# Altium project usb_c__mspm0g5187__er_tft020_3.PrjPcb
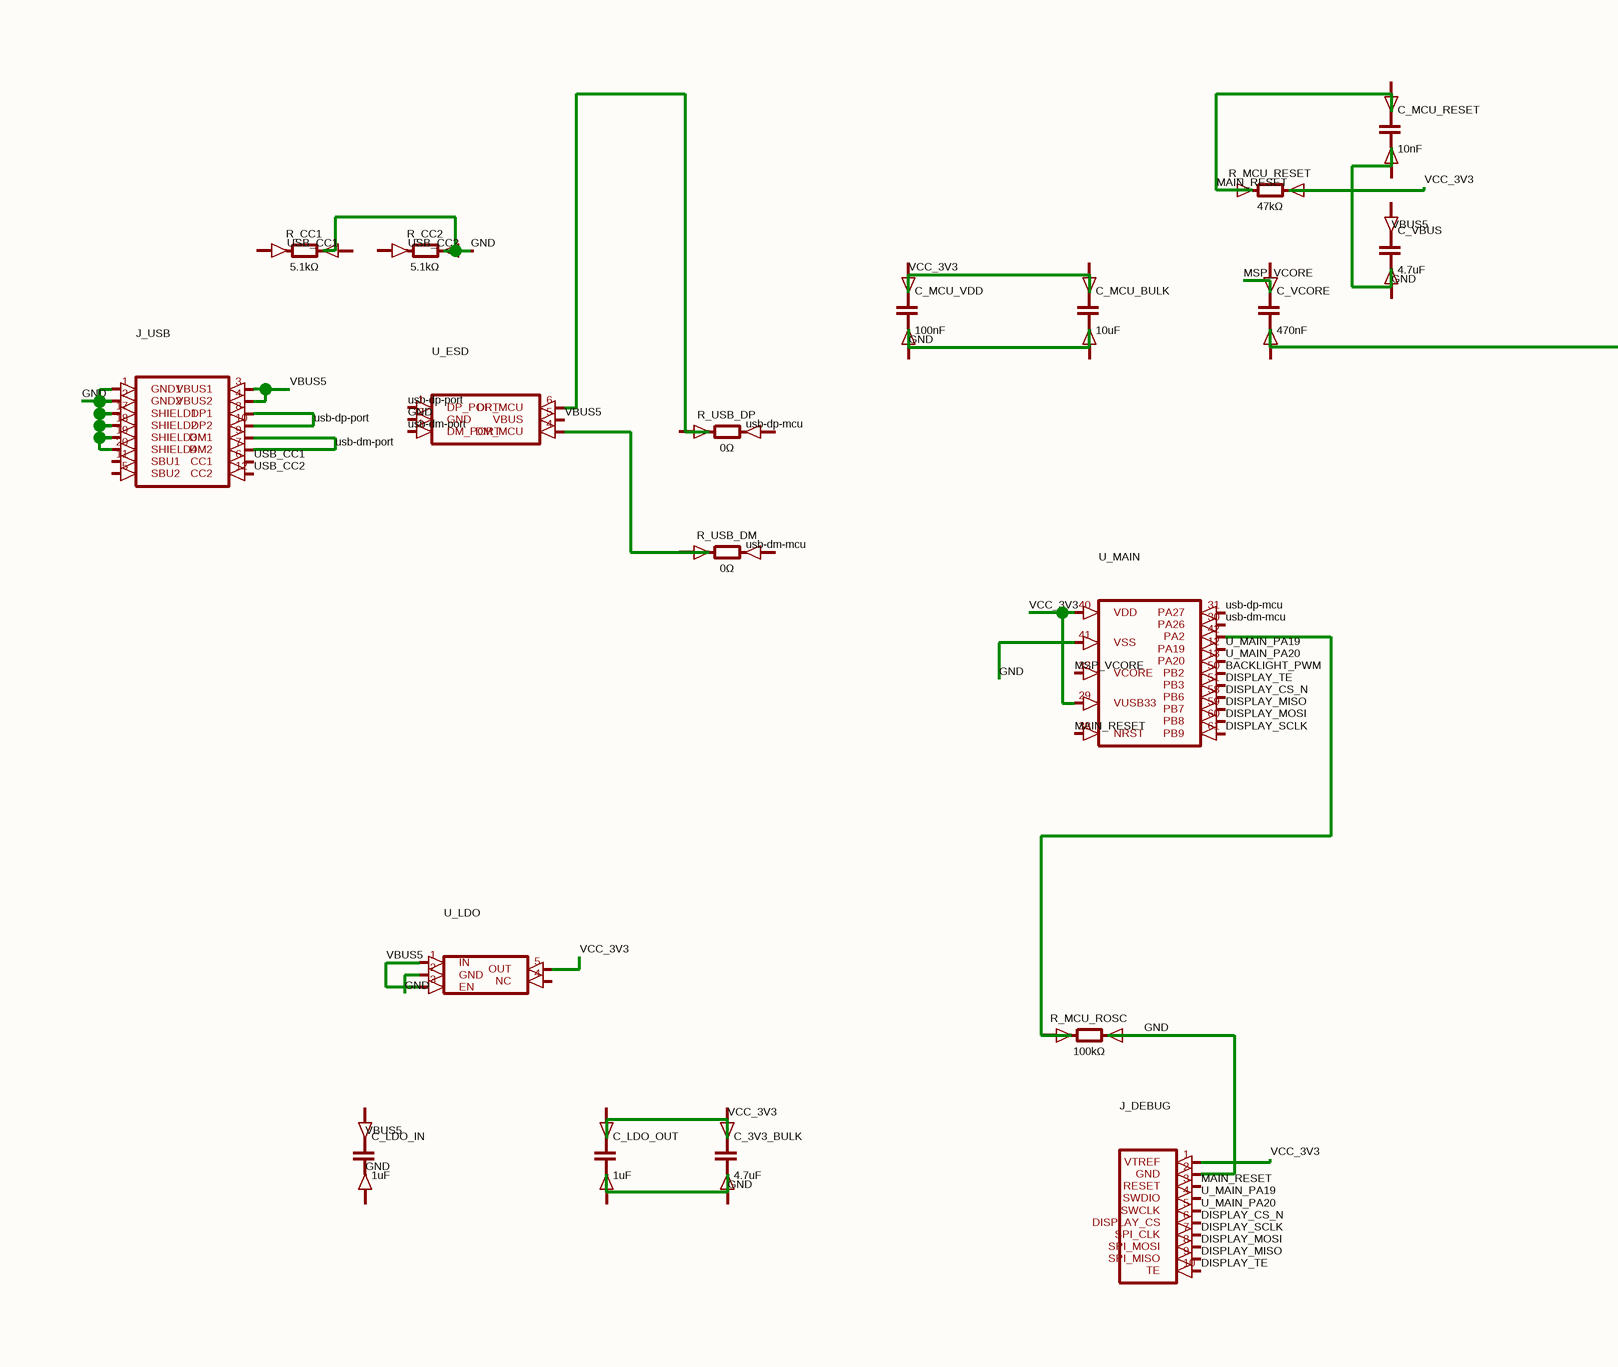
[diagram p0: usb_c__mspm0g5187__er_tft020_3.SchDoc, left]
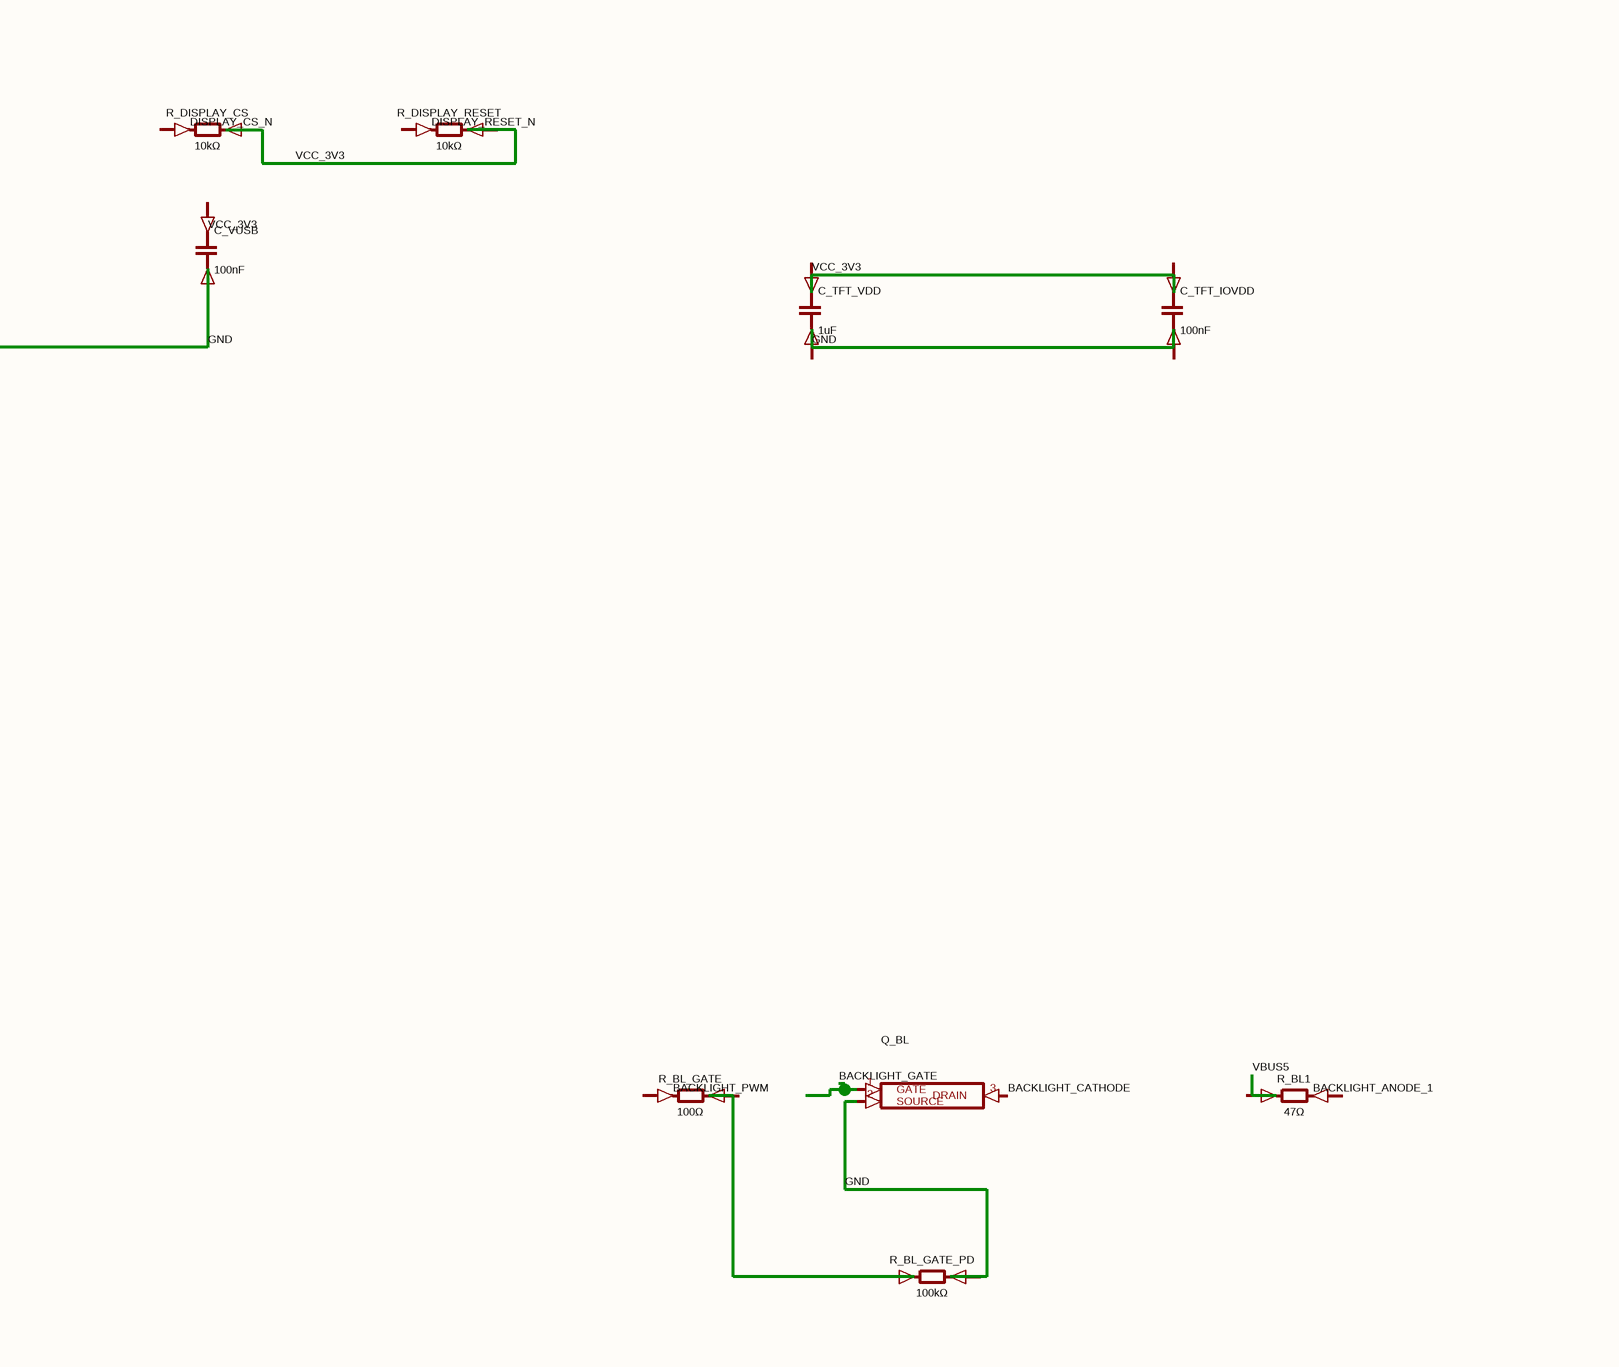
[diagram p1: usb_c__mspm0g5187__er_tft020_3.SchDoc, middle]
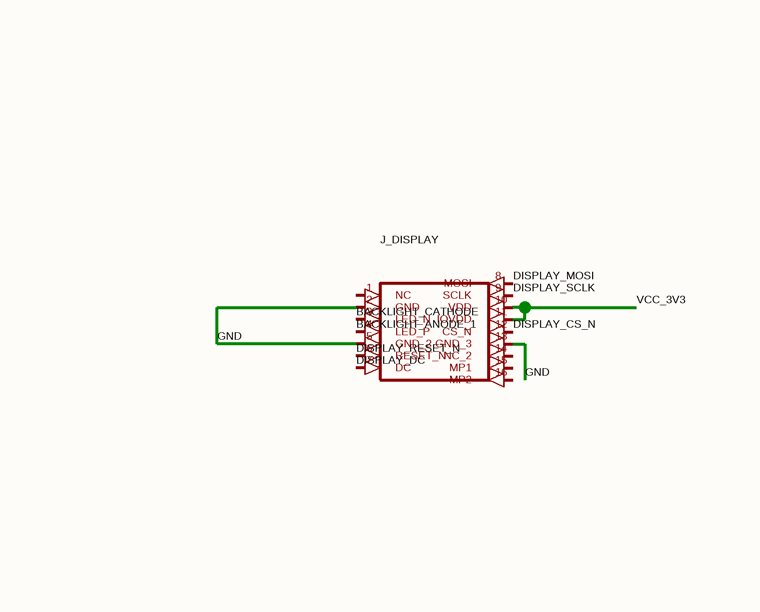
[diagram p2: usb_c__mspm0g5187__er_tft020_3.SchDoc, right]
1 sheet, 29 parts. Net scope: global (net labels, ports and power ports of the same name join across sheets).
Board file: usb_c__mspm0g5187__er_tft020_3.PcbDoc

## Sheet usb_c__mspm0g5187__er_tft020_3.SchDoc
size 386 x 150 mm

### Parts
C_3V3_BULK  4.7uF
C_LDO_IN  1uF
C_LDO_OUT  1uF
C_MCU_BULK  10uF
C_MCU_RESET  10nF
C_MCU_VDD  100nF
C_TFT_IOVDD  100nF
C_TFT_VDD  1uF
C_VBUS  4.7uF
C_VCORE  470nF
C_VUSB  100nF
J_DEBUG  (no value)
J_DISPLAY  (no value)
J_USB  (no value)
Q_BL  (no value)
R_BL1  47Ω
R_BL_GATE  100Ω
R_BL_GATE_PD  100kΩ
R_CC1  5.1kΩ
R_CC2  5.1kΩ
R_DISPLAY_CS  10kΩ
R_DISPLAY_RESET  10kΩ
R_MCU_RESET  47kΩ
R_MCU_ROSC  100kΩ
R_USB_DM  0Ω
R_USB_DP  0Ω
U_ESD  (no value)
U_LDO  (no value)
U_MAIN  (no value)

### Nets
BACKLIGHT_ANODE_1: J_DISPLAY.4(LED_P)
BACKLIGHT_CATHODE: J_DISPLAY.3(LED_N) Q_BL.3(DRAIN)
BACKLIGHT_GATE: Q_BL.1(GATE)
BACKLIGHT_PWM: U_MAIN.50(PB2)
DISPLAY_CS_N: J_DEBUG.6(DISPLAY_CS) J_DISPLAY.12(CS_N) U_MAIN.58(PB6)
DISPLAY_DC: J_DISPLAY.7(DC)
DISPLAY_MISO: J_DEBUG.9(SPI_MISO) U_MAIN.59(PB7)
DISPLAY_MOSI: J_DEBUG.8(SPI_MOSI) J_DISPLAY.8(MOSI) U_MAIN.60(PB8)
DISPLAY_RESET_N: J_DISPLAY.6(RESET_N)
DISPLAY_SCLK: J_DEBUG.7(SPI_CLK) J_DISPLAY.9(SCLK) U_MAIN.61(PB9)
DISPLAY_TE: J_DEBUG.10(TE) U_MAIN.51(PB3)
GND: C_VUSB.2(cathode) J_DEBUG.1(VTREF) J_DEBUG.2(GND) J_DISPLAY.2(GND) J_DISPLAY.5(GND_2) J_DISPLAY.10(VDD) J_DISPLAY.11(IOVDD) J_DISPLAY.13(GND_3) J_USB.1(GND1) J_USB.2(GND2) J_USB.3(VBUS1) J_USB.4(VBUS2) J_USB.17(SHIELD1) J_USB.18(SHIELD2) J_USB.19(SHIELD3) J_USB.20(SHIELD4) Q_BL.2(SOURCE) R_BL_GATE_PD.2(cathode) R_DISPLAY_CS.2(cathode) R_DISPLAY_RESET.2(cathode) R_MCU_RESET.2(cathode) R_MCU_ROSC.2(cathode) U_ESD.2(GND) U_ESD.5(VBUS) U_LDO.1(IN) U_LDO.2(GND) U_LDO.3(EN) U_LDO.5(OUT) U_MAIN.29(VUSB33) U_MAIN.40(VDD) U_MAIN.41(VSS)  [also labelled VBUS5, VCC_3V3]
MAIN_RESET: J_DEBUG.3(RESET) R_MCU_RESET.1(anode) U_MAIN.38(NRST)
MSP_VCORE: U_MAIN.32(VCORE)
U_MAIN_PA19: J_DEBUG.4(SWDIO) U_MAIN.12(PA19)
U_MAIN_PA20: J_DEBUG.5(SWCLK) U_MAIN.13(PA20)
usb-dm-mcu: U_MAIN.30(PA26)
usb-dm-port: J_USB.7(DM2) J_USB.9(DM1) U_ESD.3(DM_PORT)
usb-dp-mcu: U_MAIN.31(PA27)
usb-dp-port: J_USB.8(DP1) J_USB.10(DP2) U_ESD.1(DP_PORT)
USB_CC1: J_USB.6(CC1)
USB_CC2: J_USB.12(CC2)
NetR_MCU_ROSC_1: R_MCU_ROSC.1(anode) U_MAIN.42(PA2)
NetR_USB_DM_1: R_USB_DM.1(anode) U_ESD.4(DM_MCU)

Not connected (* = marked no-connect by the designer): C_3V3_BULK 1(anode) 2(cathode); C_LDO_IN 1(anode) 2(cathode); C_LDO_OUT 1(anode) 2(cathode); C_MCU_BULK 1(anode) 2(cathode); C_MCU_RESET 1(anode) 2(cathode); C_MCU_VDD 1(anode) 2(cathode); C_TFT_IOVDD 1(anode) 2(cathode); C_TFT_VDD 1(anode) 2(cathode); C_VBUS 1(anode) 2(cathode); C_VCORE 1(anode) 2(cathode); C_VUSB 1(anode); J_DISPLAY 1(NC) 14(NC_2) 15(MP1) 16(MP2); J_USB 5(SBU2) 11(SBU1); R_BL1 1(anode) 2(cathode); R_BL_GATE 1(anode) 2(cathode); R_BL_GATE_PD 1(anode); R_CC1 1(anode) 2(cathode); R_CC2 1(anode) 2(cathode); R_DISPLAY_CS 1(anode); R_DISPLAY_RESET 1(anode); R_USB_DM 2(cathode); R_USB_DP 1(anode) 2(cathode); U_ESD 6(DP_MCU); U_LDO 4(NC)

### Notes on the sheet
- Labels drawn without touching a wire or pin: BACKLIGHT_ANODE_1, BACKLIGHT_PWM, DISPLAY_CS_N, DISPLAY_RESET_N, GND, usb-dm-mcu, usb-dp-mcu, USB_CC1, USB_CC2, VBUS5, VCC_3V3

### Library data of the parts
C_3V3_BULK C_LDO_IN C_LDO_OUT C_MCU_BULK C_MCU_RESET C_MCU_VDD C_TFT_IOVDD C_TFT_VDD C_VBUS C_VCORE C_VUSB = capacitor_down
J_DEBUG = J_DEBUG
J_DISPLAY = J_DISPLAY
J_USB = J_USB
Q_BL = Q_BL
R_BL1 R_BL_GATE R_BL_GATE_PD R_CC1 R_CC2 R_DISPLAY_CS R_DISPLAY_RESET R_MCU_RESET R_MCU_ROSC R_USB_DM R_USB_DP = boxresistor_right
U_ESD = U_ESD
U_LDO = U_LDO
U_MAIN = U_MAIN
